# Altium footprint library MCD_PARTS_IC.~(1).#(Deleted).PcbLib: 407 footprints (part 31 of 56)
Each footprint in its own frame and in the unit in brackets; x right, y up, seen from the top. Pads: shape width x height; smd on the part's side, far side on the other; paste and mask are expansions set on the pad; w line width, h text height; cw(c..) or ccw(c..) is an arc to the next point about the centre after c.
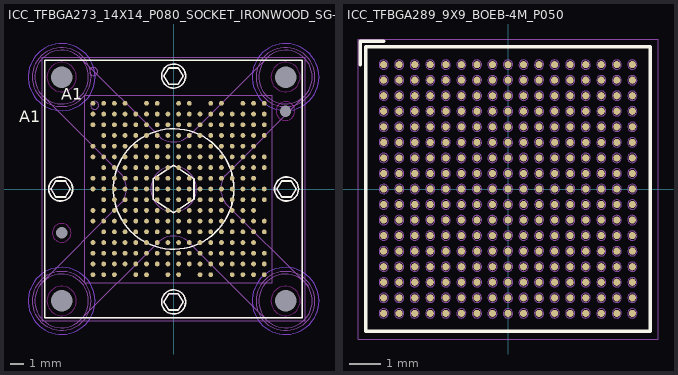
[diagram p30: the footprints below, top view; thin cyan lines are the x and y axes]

## ICC_TFBGA273_14X14_P080_SOCKET_IRONWOOD_SG-BGA-6112MF_WITHOUT-3D-SOCKET [mm] "MCD-03616"
height 1.2
pads (279):
  round 0.36 smd mask+0.05: A1(-6.025,6.4) A2(-5.225,6.4) A3(-4.425,6.4) A4(-3.625,6.4) A6(-2.025,6.4) A7(-1.225,6.4) A9(0.375,6.4) A10(1.175,6.4) A12(2.775,6.4) A13(3.575,6.4) A15(5.175,6.4) A16(5.975,6.4) A17(6.775,6.4) B1(-6.025,5.6) B2(-5.225,5.6) B3(-4.425,5.6) B4(-3.625,5.6) B5(-2.825,5.6) B6(-2.025,5.6) B7(-1.225,5.6) B8(-0.425,5.6) B9(0.375,5.6) B10(1.175,5.6) B11(1.975,5.6) B12(2.775,5.6) B13(3.575,5.6) B14(4.375,5.6) B15(5.175,5.6) B16(5.975,5.6) B17(6.775,5.6) C1(-6.025,4.8) C2(-5.225,4.8) C3(-4.425,4.8) C4(-3.625,4.8) C5(-2.825,4.8) C6(-2.025,4.8) C7(-1.225,4.8) C8(-0.425,4.8) C9(0.375,4.8) C10(1.175,4.8) C11(1.975,4.8) C12(2.775,4.8) C13(3.575,4.8) C14(4.375,4.8) C15(5.175,4.8) C16(5.975,4.8) C17(6.775,4.8) D2(-5.225,4) D3(-4.425,4) D4(-3.625,4) D5(-2.825,4) D6(-2.025,4) D7(-1.225,4) D8(-0.425,4) D9(0.375,4) D10(1.175,4) D11(1.975,4) D12(2.775,4) D13(3.575,4) D14(4.375,4) D15(5.175,4) D16(5.975,4) D17(6.775,4) E1(-6.025,3.2) E2(-5.225,3.2) E3(-4.425,3.2) E4(-3.625,3.2) E5(-2.825,3.2) E6(-2.025,3.2) E7(-1.225,3.2) E8(-0.425,3.2) E9(0.375,3.2) E10(1.175,3.2) E11(1.975,3.2) E12(2.775,3.2) E13(3.575,3.2) E14(4.375,3.2) E15(5.175,3.2) E16(5.975,3.2) F1(-6.025,2.4) F2(-5.225,2.4) F3(-4.425,2.4) F4(-3.625,2.4) F5(-2.825,2.4) F6(-2.025,2.4) F7(-1.225,2.4) F8(-0.425,2.4) F9(0.375,2.4) F10(1.175,2.4) F11(1.975,2.4) F12(2.775,2.4) F13(3.575,2.4) F14(4.375,2.4) F15(5.175,2.4) F16(5.975,2.4) F17(6.775,2.4) G2(-5.225,1.6) G3(-4.425,1.6) G4(-3.625,1.6) G5(-2.825,1.6) G6(-2.025,1.6) G7(-1.225,1.6) G8(-0.425,1.6) G9(0.375,1.6) G10(1.175,1.6) G11(1.975,1.6) G12(2.775,1.6) G13(3.575,1.6) G14(4.375,1.6) G15(5.175,1.6) G16(5.975,1.6) G17(6.775,1.6) H1(-6.025,0.8) H2(-5.225,0.8) H3(-4.425,0.8) H4(-3.625,0.8) H5(-2.825,0.8) H6(-2.025,0.8) H7(-1.225,0.8) H8(-0.425,0.8) H9(0.375,0.8) H10(1.175,0.8) H11(1.975,0.8) H12(2.775,0.8) H13(3.575,0.8) H14(4.375,0.8) H15(5.175,0.8) H16(5.975,0.8) J1(-6.025,0) J2(-5.225,0) J3(-4.425,0) J4(-3.625,0) J5(-2.825,0) J6(-2.025,0) J7(-1.225,0) J8(-0.425,0) J9(0.375,0) J10(1.175,0) J11(1.975,0) J12(2.775,0) J13(3.575,0) J14(4.375,0) J15(5.175,0) J16(5.975,0) J17(6.775,0) K2(-5.225,-0.8) K3(-4.425,-0.8) K4(-3.625,-0.8) K5(-2.825,-0.8) K6(-2.025,-0.8) K7(-1.225,-0.8) K8(-0.425,-0.8) K9(0.375,-0.8) K10(1.175,-0.8) K11(1.975,-0.8) K12(2.775,-0.8) K13(3.575,-0.8) K14(4.375,-0.8) K15(5.175,-0.8) K16(5.975,-0.8) K17(6.775,-0.8) L1(-6.025,-1.6) L2(-5.225,-1.6) L3(-4.425,-1.6) L4(-3.625,-1.6) L5(-2.825,-1.6) L6(-2.025,-1.6) L7(-1.225,-1.6) L8(-0.425,-1.6) L9(0.375,-1.6) L10(1.175,-1.6) L11(1.975,-1.6) L12(2.775,-1.6) L13(3.575,-1.6) L14(4.375,-1.6) L15(5.175,-1.6) L16(5.975,-1.6) M1(-6.025,-2.4) M2(-5.225,-2.4) M3(-4.425,-2.4) M4(-3.625,-2.4) M5(-2.825,-2.4) M6(-2.025,-2.4) M7(-1.225,-2.4) M8(-0.425,-2.4) M9(0.375,-2.4) M10(1.175,-2.4) M11(1.975,-2.4) M12(2.775,-2.4) M13(3.575,-2.4) M14(4.375,-2.4) M15(5.175,-2.4) M16(5.975,-2.4) M17(6.775,-2.4) N2(-5.225,-3.2) N3(-4.425,-3.2) N4(-3.625,-3.2) N5(-2.825,-3.2) N6(-2.025,-3.2) N7(-1.225,-3.2) N8(-0.425,-3.2) N9(0.375,-3.2) N10(1.175,-3.2) N11(1.975,-3.2) N12(2.775,-3.2) N13(3.575,-3.2) N14(4.375,-3.2) N15(5.175,-3.2) N16(5.975,-3.2) N17(6.775,-3.2) P1(-6.025,-4) P2(-5.225,-4) P3(-4.425,-4) P4(-3.625,-4) P5(-2.825,-4) P6(-2.025,-4) P7(-1.225,-4) P8(-0.425,-4) P9(0.375,-4) P10(1.175,-4) P11(1.975,-4) P12(2.775,-4) P13(3.575,-4) P14(4.375,-4) P15(5.175,-4) P16(5.975,-4) R1(-6.025,-4.8) R2(-5.225,-4.8) R3(-4.425,-4.8) R4(-3.625,-4.8) R5(-2.825,-4.8) R6(-2.025,-4.8) R7(-1.225,-4.8) R8(-0.425,-4.8) R9(0.375,-4.8) R10(1.175,-4.8) R11(1.975,-4.8) R12(2.775,-4.8) R13(3.575,-4.8) R14(4.375,-4.8) R15(5.175,-4.8) R16(5.975,-4.8) R17(6.775,-4.8) T1(-6.025,-5.6) T2(-5.225,-5.6) T3(-4.425,-5.6) T4(-3.625,-5.6) T5(-2.825,-5.6) T6(-2.025,-5.6) T7(-1.225,-5.6) T8(-0.425,-5.6) T9(0.375,-5.6) T10(1.175,-5.6) T11(1.975,-5.6) T12(2.775,-5.6) T13(3.575,-5.6) T14(4.375,-5.6) T15(5.175,-5.6) T16(5.975,-5.6) T17(6.775,-5.6) U1(-6.025,-6.4) U2(-5.225,-6.4) U3(-4.425,-6.4) U5(-2.825,-6.4) U6(-2.025,-6.4) U8(-0.425,-6.4) U9(0.375,-6.4) U11(1.975,-6.4) U12(2.775,-6.4) U14(4.375,-6.4) U15(5.175,-6.4) U16(5.975,-6.4) U17(6.775,-6.4)
  round 0 hole 1.61 unplated mask+0.05: NPTH1(-8.363,8.363) NPTH2(8.363,8.363) NPTH3(8.363,-8.363) NPTH4(-8.363,-8.363)
  round 0 hole 0.85 unplated mask+0.05: NPTH5(-8.363,-3.283) NPTH6(8.363,5.823)
Bottom Layer keep-out:
  circle w0.01: c-8.362,8.362 r2.5
  circle w0.01: c8.363,8.363 r2.5
  circle w0.01: c8.363,-8.363 r2.5
  circle w0.01: c-8.363,-8.363 r2.5
Top Overlay:
  circle w0.12: c0,0 r4.5
  circle w0.12: c-8.438,0 r0.9
  circle w0.12: c0,-8.438 r0.9
  circle w0.12: c8.438,0 r0.9
  circle w0.12: c0,8.437 r0.9
  lines w0.12: -9.613,-9.613 9.613,-9.613 9.613,9.613 -9.613,9.613 -9.613,-9.613 ; -9.158,0 -8.798,0.6 -8.078,0.6 -7.718,0 -8.078,-0.6 -8.798,-0.6 -9.158,0 ; -1.524,-0.762 0,-1.778 1.524,-0.762 1.524,0.762 0,1.778 -1.524,0.762 -1.524,-0.762 ; -0.72,-8.438 -0.36,-7.838 0.36,-7.838 0.72,-8.438 0.36,-9.038 -0.36,-9.038 -0.72,-8.438 ; -0.72,8.437 -0.36,7.837 0.36,7.837 0.72,8.437 0.36,9.037 -0.36,9.037 -0.72,8.437 ; 7.718,0 8.078,0.6 8.798,0.6 9.158,0 8.798,-0.6 8.078,-0.6 7.718,0
  text "A1" at -8.4,6.375 h1.5
  text "A1" at -11.55,4.675 h1.5
Bottom Overlay:
  circle w0.12: c-8.363,8.363 r2.5
  circle w0.12: c-8.362,-8.362 r2.5
  circle w0.12: c8.362,-8.362 r2.5
  circle w0.12: c8.363,8.363 r2.5
Keep-Out Layer:
  circle w0.01: c8.363,5.823 r0.7
  circle w0.01: c-8.363,-3.283 r0.7
  circle w0.01: c-8.362,8.362 r1.1
  circle w0.01: c8.363,8.363 r1.1
  circle w0.01: c8.362,-8.362 r1.1
  circle w0.01: c-8.363,-8.363 r1.1
M14-Top Assembly:
  circle w0.01: c-5.9,6.25 r0.3
  circle w0.01: c0,0 r4.5
  circle w0.01: c-8.438,0 r0.9
  circle w0.01: c0,-8.438 r0.9
  circle w0.01: c8.438,0 r0.9
  circle w0.01: c0,8.437 r0.9
  circle w0.01: c-5.975,8.775 r0.3
  lines w0.01: -9.613,-9.613 9.613,-9.613 9.613,3.562 9.613,9.613 -9.613,9.613 -9.613,-9.613 ; -9.158,0 -8.798,-0.6 -8.078,-0.6 -7.718,0 -8.078,0.6 -8.798,0.6 -9.158,0 ; -6.625,-7 7.375,-7 7.375,7 -6.625,7 -6.625,-7 ; -1.524,-0.762 0,-1.778 1.524,-0.762 1.524,0.762 0,1.778 -1.524,0.762 -1.524,-0.762 ; -0.72,-8.438 -0.36,-9.038 0.36,-9.038 0.72,-8.438 0.36,-7.838 -0.36,-7.838 -0.72,-8.438 ; -0.72,8.437 -0.36,9.037 0.36,9.037 0.72,8.437 0.36,7.837 -0.36,7.837 -0.72,8.437 ; 7.718,0 8.078,-0.6 8.798,-0.6 9.158,0 8.798,0.6 8.078,0.6 7.718,0
  text "'.Designator'" at 0,0 h0.75
M15-Bottom Assembly:
  circle w0.01: c-8.362,8.362 r2
  circle w0.01: c-8.362,-8.362 r2
  circle w0.01: c8.363,-8.363 r2
  circle w0.01: c8.362,8.362 r2
  lines w0.01: -10.044,7.235 -3.82,1.011 ; -9.929,-7.075 -3.82,-0.967 ; -7.235,-10.044 -1.011,-3.82 ; -7.075,9.929 -0.967,3.82 ; -3.848,1.029 cw(c-5.325,0) -3.826,-0.996 ; -1.029,-3.848 cw(c0,-5.325) 0.996,-3.826 ; -0.996,3.826 ccw(c0,5.325) 1.029,3.848 ; 0.967,-3.82 7.075,-9.929 ; 1.011,3.82 7.235,10.044 ; 3.82,-1.011 10.044,-7.235 ; 3.82,0.967 9.928,7.075 ; 3.826,0.996 ccw(c5.325,0) 3.848,-1.029
M16-Top Courtyard:
  lines w0.01: -9.825,-9.825 -9.825,9.825 9.825,9.825 9.825,-9.825 -9.825,-9.825
M17-Bottom Courtyard:
  circle w0.01: c0,0 r1.7
  circle w0.01: c-8.362,8.362 r2.2
  circle w0.01: c8.362,8.362 r2.2
  circle w0.01: c8.362,-8.362 r2.2
  circle w0.01: c-8.362,-8.362 r2.2
3D body: height 0.37, standoff -0.03, extent -0.625,-6.6 -0.225,-6.2
3D body: height 0.37, standoff -0.03, extent 6.575,-6.6 6.975,-6.2
3D body: height 0.37, standoff -0.03, extent 5.775,-6.6 6.175,-6.2
3D body: height 0.37, standoff -0.03, extent 4.975,-6.6 5.375,-6.2
3D body: height 0.37, standoff -0.03, extent 4.175,-6.6 4.575,-6.2
3D body: height 0.37, standoff -0.03, extent 2.575,-6.6 2.975,-6.2
3D body: height 0.37, standoff -0.03, extent 1.775,-6.6 2.175,-6.2
3D body: height 0.37, standoff -0.03, extent 0.175,-6.6 0.575,-6.2
3D body: height 0.37, standoff -0.03, extent -2.225,-6.6 -1.825,-6.2
3D body: height 0.37, standoff -0.03, extent -3.025,-6.6 -2.625,-6.2
3D body: height 0.37, standoff -0.03, extent -4.625,-6.6 -4.225,-6.2
3D body: height 0.37, standoff -0.03, extent -5.425,-6.6 -5.025,-6.2
3D body: height 0.37, standoff -0.03, extent -6.225,-6.6 -5.825,-6.2
3D body: height 0.37, standoff -0.03, extent 6.575,-5.8 6.975,-5.4
3D body: height 0.37, standoff -0.03, extent 5.775,-5.8 6.175,-5.4
3D body: height 0.37, standoff -0.03, extent 4.975,-5.8 5.375,-5.4
3D body: height 0.37, standoff -0.03, extent 4.175,-5.8 4.575,-5.4
3D body: height 0.37, standoff -0.03, extent 3.375,-5.8 3.775,-5.4
3D body: height 0.37, standoff -0.03, extent 2.575,-5.8 2.975,-5.4
3D body: height 0.37, standoff -0.03, extent 1.775,-5.8 2.175,-5.4
3D body: height 0.37, standoff -0.03, extent 0.975,-5.8 1.375,-5.4
3D body: height 0.37, standoff -0.03, extent 0.175,-5.8 0.575,-5.4
3D body: height 0.37, standoff -0.03, extent -0.625,-5.8 -0.225,-5.4
3D body: height 0.37, standoff -0.03, extent -1.425,-5.8 -1.025,-5.4
3D body: height 0.37, standoff -0.03, extent -2.225,-5.8 -1.825,-5.4
3D body: height 0.37, standoff -0.03, extent -3.025,-5.8 -2.625,-5.4
3D body: height 0.37, standoff -0.03, extent -3.825,-5.8 -3.425,-5.4
3D body: height 0.37, standoff -0.03, extent -4.625,-5.8 -4.225,-5.4
3D body: height 0.37, standoff -0.03, extent -5.425,-5.8 -5.025,-5.4
3D body: height 0.37, standoff -0.03, extent -6.225,-5.8 -5.825,-5.4
3D body: height 0.37, standoff -0.03, extent 6.575,-5 6.975,-4.6
3D body: height 0.37, standoff -0.03, extent 5.775,-5 6.175,-4.6
3D body: height 0.37, standoff -0.03, extent 4.975,-5 5.375,-4.6
3D body: height 0.37, standoff -0.03, extent 4.175,-5 4.575,-4.6
3D body: height 0.37, standoff -0.03, extent 3.375,-5 3.775,-4.6
3D body: height 0.37, standoff -0.03, extent 2.575,-5 2.975,-4.6
3D body: height 0.37, standoff -0.03, extent 1.775,-5 2.175,-4.6
3D body: height 0.37, standoff -0.03, extent 0.975,-5 1.375,-4.6
3D body: height 0.37, standoff -0.03, extent 0.175,-5 0.575,-4.6
3D body: height 0.37, standoff -0.03, extent -0.625,-5 -0.225,-4.6
3D body: height 0.37, standoff -0.03, extent -1.425,-5 -1.025,-4.6
3D body: height 0.37, standoff -0.03, extent -2.225,-5 -1.825,-4.6
3D body: height 0.37, standoff -0.03, extent -3.025,-5 -2.625,-4.6
3D body: height 0.37, standoff -0.03, extent -3.825,-5 -3.425,-4.6
3D body: height 0.37, standoff -0.03, extent -4.625,-5 -4.225,-4.6
3D body: height 0.37, standoff -0.03, extent -5.425,-5 -5.025,-4.6
3D body: height 0.37, standoff -0.03, extent -6.225,-5 -5.825,-4.6
3D body: height 0.37, standoff -0.03, extent 5.775,-4.2 6.175,-3.8
3D body: height 0.37, standoff -0.03, extent 4.975,-4.2 5.375,-3.8
3D body: height 0.37, standoff -0.03, extent 4.175,-4.2 4.575,-3.8
3D body: height 0.37, standoff -0.03, extent 3.375,-4.2 3.775,-3.8
3D body: height 0.37, standoff -0.03, extent 2.575,-4.2 2.975,-3.8
3D body: height 0.37, standoff -0.03, extent 1.775,-4.2 2.175,-3.8
3D body: height 0.37, standoff -0.03, extent 0.975,-4.2 1.375,-3.8
3D body: height 0.37, standoff -0.03, extent 0.175,-4.2 0.575,-3.8
3D body: height 0.37, standoff -0.03, extent -0.625,-4.2 -0.225,-3.8
3D body: height 0.37, standoff -0.03, extent -1.425,-4.2 -1.025,-3.8
3D body: height 0.37, standoff -0.03, extent -2.225,-4.2 -1.825,-3.8
3D body: height 0.37, standoff -0.03, extent -3.025,-4.2 -2.625,-3.8
3D body: height 0.37, standoff -0.03, extent -3.825,-4.2 -3.425,-3.8
3D body: height 0.37, standoff -0.03, extent -4.625,-4.2 -4.225,-3.8
3D body: height 0.37, standoff -0.03, extent -5.425,-4.2 -5.025,-3.8
3D body: height 0.37, standoff -0.03, extent -6.225,-4.2 -5.825,-3.8
3D body: height 0.37, standoff -0.03, extent 6.575,-3.4 6.975,-3
3D body: height 0.37, standoff -0.03, extent 5.775,-3.4 6.175,-3
3D body: height 0.37, standoff -0.03, extent 4.975,-3.4 5.375,-3
3D body: height 0.37, standoff -0.03, extent 4.175,-3.4 4.575,-3
3D body: height 0.37, standoff -0.03, extent 3.375,-3.4 3.775,-3
3D body: height 0.37, standoff -0.03, extent 2.575,-3.4 2.975,-3
3D body: height 0.37, standoff -0.03, extent 1.775,-3.4 2.175,-3
3D body: height 0.37, standoff -0.03, extent 0.975,-3.4 1.375,-3
3D body: height 0.37, standoff -0.03, extent 0.175,-3.4 0.575,-3
3D body: height 0.37, standoff -0.03, extent -0.625,-3.4 -0.225,-3
3D body: height 0.37, standoff -0.03, extent -1.425,-3.4 -1.025,-3
3D body: height 0.37, standoff -0.03, extent -2.225,-3.4 -1.825,-3
3D body: height 0.37, standoff -0.03, extent -3.025,-3.4 -2.625,-3
3D body: height 0.37, standoff -0.03, extent -3.825,-3.4 -3.425,-3
3D body: height 0.37, standoff -0.03, extent -4.625,-3.4 -4.225,-3
3D body: height 0.37, standoff -0.03, extent -5.425,-3.4 -5.025,-3
3D body: height 0.37, standoff -0.03, extent 6.575,-2.6 6.975,-2.2
3D body: height 0.37, standoff -0.03, extent 5.775,-2.6 6.175,-2.2
3D body: height 0.37, standoff -0.03, extent 4.975,-2.6 5.375,-2.2
3D body: height 0.37, standoff -0.03, extent 4.175,-2.6 4.575,-2.2
3D body: height 0.37, standoff -0.03, extent 3.375,-2.6 3.775,-2.2
3D body: height 0.37, standoff -0.03, extent 2.575,-2.6 2.975,-2.2
3D body: height 0.37, standoff -0.03, extent 1.775,-2.6 2.175,-2.2
3D body: height 0.37, standoff -0.03, extent 0.975,-2.6 1.375,-2.2
3D body: height 0.37, standoff -0.03, extent 0.175,-2.6 0.575,-2.2
3D body: height 0.37, standoff -0.03, extent -0.625,-2.6 -0.225,-2.2
3D body: height 0.37, standoff -0.03, extent -1.425,-2.6 -1.025,-2.2
3D body: height 0.37, standoff -0.03, extent -2.225,-2.6 -1.825,-2.2
3D body: height 0.37, standoff -0.03, extent -3.025,-2.6 -2.625,-2.2
3D body: height 0.37, standoff -0.03, extent -3.825,-2.6 -3.425,-2.2
3D body: height 0.37, standoff -0.03, extent -4.625,-2.6 -4.225,-2.2
3D body: height 0.37, standoff -0.03, extent -5.425,-2.6 -5.025,-2.2
3D body: height 0.37, standoff -0.03, extent -6.225,-2.6 -5.825,-2.2
3D body: height 0.37, standoff -0.03, extent 5.775,-1.8 6.175,-1.4
3D body: height 0.37, standoff -0.03, extent 4.975,-1.8 5.375,-1.4
3D body: height 0.37, standoff -0.03, extent 4.175,-1.8 4.575,-1.4
3D body: height 0.37, standoff -0.03, extent 3.375,-1.8 3.775,-1.4
3D body: height 0.37, standoff -0.03, extent 2.575,-1.8 2.975,-1.4
3D body: height 0.37, standoff -0.03, extent 1.775,-1.8 2.175,-1.4
3D body: height 0.37, standoff -0.03, extent 0.975,-1.8 1.375,-1.4
3D body: height 0.37, standoff -0.03, extent 0.175,-1.8 0.575,-1.4
3D body: height 0.37, standoff -0.03, extent -0.625,-1.8 -0.225,-1.4
3D body: height 0.37, standoff -0.03, extent -1.425,-1.8 -1.025,-1.4
3D body: height 0.37, standoff -0.03, extent -2.225,-1.8 -1.825,-1.4
3D body: height 0.37, standoff -0.03, extent -3.025,-1.8 -2.625,-1.4
3D body: height 0.37, standoff -0.03, extent -3.825,-1.8 -3.425,-1.4
3D body: height 0.37, standoff -0.03, extent -4.625,-1.8 -4.225,-1.4
3D body: height 0.37, standoff -0.03, extent -5.425,-1.8 -5.025,-1.4
3D body: height 0.37, standoff -0.03, extent -6.225,-1.8 -5.825,-1.4
3D body: height 0.37, standoff -0.03, extent 6.575,-1 6.975,-0.6
3D body: height 0.37, standoff -0.03, extent 5.775,-1 6.175,-0.6
3D body: height 0.37, standoff -0.03, extent 4.975,-1 5.375,-0.6
3D body: height 0.37, standoff -0.03, extent 4.175,-1 4.575,-0.6
3D body: height 0.37, standoff -0.03, extent 3.375,-1 3.775,-0.6
3D body: height 0.37, standoff -0.03, extent 2.575,-1 2.975,-0.6
3D body: height 0.37, standoff -0.03, extent 1.775,-1 2.175,-0.6
3D body: height 0.37, standoff -0.03, extent 0.975,-1 1.375,-0.6
3D body: height 0.37, standoff -0.03, extent 0.175,-1 0.575,-0.6
3D body: height 0.37, standoff -0.03, extent -0.625,-1 -0.225,-0.6
3D body: height 0.37, standoff -0.03, extent -1.425,-1 -1.025,-0.6
3D body: height 0.37, standoff -0.03, extent -2.225,-1 -1.825,-0.6
3D body: height 0.37, standoff -0.03, extent -3.025,-1 -2.625,-0.6
3D body: height 0.37, standoff -0.03, extent -3.825,-1 -3.425,-0.6
3D body: height 0.37, standoff -0.03, extent -4.625,-1 -4.225,-0.6
3D body: height 0.37, standoff -0.03, extent -5.425,-1 -5.025,-0.6
3D body: height 0.37, standoff -0.03, extent 6.575,-0.2 6.975,0.2
3D body: height 0.37, standoff -0.03, extent 5.775,-0.2 6.175,0.2
3D body: height 0.37, standoff -0.03, extent 4.975,-0.2 5.375,0.2
3D body: height 0.37, standoff -0.03, extent 4.175,-0.2 4.575,0.2
3D body: height 0.37, standoff -0.03, extent 3.375,-0.2 3.775,0.2
3D body: height 0.37, standoff -0.03, extent 2.575,-0.2 2.975,0.2
3D body: height 0.37, standoff -0.03, extent 1.775,-0.2 2.175,0.2
3D body: height 0.37, standoff -0.03, extent 0.975,-0.2 1.375,0.2
3D body: height 0.37, standoff -0.03, extent 0.175,-0.2 0.575,0.2
3D body: height 0.37, standoff -0.03, extent -0.625,-0.2 -0.225,0.2
3D body: height 0.37, standoff -0.03, extent -1.425,-0.2 -1.025,0.2
3D body: height 0.37, standoff -0.03, extent -2.225,-0.2 -1.825,0.2
3D body: height 0.37, standoff -0.03, extent -3.025,-0.2 -2.625,0.2
3D body: height 0.37, standoff -0.03, extent -3.825,-0.2 -3.425,0.2
3D body: height 0.37, standoff -0.03, extent -4.625,-0.2 -4.225,0.2
3D body: height 0.37, standoff -0.03, extent -5.425,-0.2 -5.025,0.2
3D body: height 0.37, standoff -0.03, extent -6.225,-0.2 -5.825,0.2
3D body: height 0.37, standoff -0.03, extent 5.775,0.6 6.175,1
3D body: height 0.37, standoff -0.03, extent 4.975,0.6 5.375,1
3D body: height 0.37, standoff -0.03, extent 4.175,0.6 4.575,1
3D body: height 0.37, standoff -0.03, extent 3.375,0.6 3.775,1
3D body: height 0.37, standoff -0.03, extent 2.575,0.6 2.975,1
3D body: height 0.37, standoff -0.03, extent 1.775,0.6 2.175,1
3D body: height 0.37, standoff -0.03, extent 0.975,0.6 1.375,1
3D body: height 0.37, standoff -0.03, extent 0.175,0.6 0.575,1
3D body: height 0.37, standoff -0.03, extent -0.625,0.6 -0.225,1
3D body: height 0.37, standoff -0.03, extent -1.425,0.6 -1.025,1
3D body: height 0.37, standoff -0.03, extent -2.225,0.6 -1.825,1
3D body: height 0.37, standoff -0.03, extent -3.025,0.6 -2.625,1
3D body: height 0.37, standoff -0.03, extent -3.825,0.6 -3.425,1
3D body: height 0.37, standoff -0.03, extent -4.625,0.6 -4.225,1
3D body: height 0.37, standoff -0.03, extent -5.425,0.6 -5.025,1
3D body: height 0.37, standoff -0.03, extent -6.225,0.6 -5.825,1
3D body: height 0.37, standoff -0.03, extent 6.575,1.4 6.975,1.8
3D body: height 0.37, standoff -0.03, extent 5.775,1.4 6.175,1.8
3D body: height 0.37, standoff -0.03, extent 4.975,1.4 5.375,1.8
3D body: height 0.37, standoff -0.03, extent 4.175,1.4 4.575,1.8
3D body: height 0.37, standoff -0.03, extent 3.375,1.4 3.775,1.8
3D body: height 0.37, standoff -0.03, extent 2.575,1.4 2.975,1.8
3D body: height 0.37, standoff -0.03, extent 1.775,1.4 2.175,1.8
3D body: height 0.37, standoff -0.03, extent 0.975,1.4 1.375,1.8
3D body: height 0.37, standoff -0.03, extent 0.175,1.4 0.575,1.8
3D body: height 0.37, standoff -0.03, extent -0.625,1.4 -0.225,1.8
3D body: height 0.37, standoff -0.03, extent -1.425,1.4 -1.025,1.8
3D body: height 0.37, standoff -0.03, extent -2.225,1.4 -1.825,1.8
3D body: height 0.37, standoff -0.03, extent -3.025,1.4 -2.625,1.8
3D body: height 0.37, standoff -0.03, extent -3.825,1.4 -3.425,1.8
3D body: height 0.37, standoff -0.03, extent -4.625,1.4 -4.225,1.8
3D body: height 0.37, standoff -0.03, extent -5.425,1.4 -5.025,1.8
3D body: height 0.37, standoff -0.03, extent 6.575,2.2 6.975,2.6
3D body: height 0.37, standoff -0.03, extent 5.775,2.2 6.175,2.6
3D body: height 0.37, standoff -0.03, extent 4.975,2.2 5.375,2.6
3D body: height 0.37, standoff -0.03, extent 4.175,2.2 4.575,2.6
3D body: height 0.37, standoff -0.03, extent 3.375,2.2 3.775,2.6
3D body: height 0.37, standoff -0.03, extent 2.575,2.2 2.975,2.6
3D body: height 0.37, standoff -0.03, extent 1.775,2.2 2.175,2.6
3D body: height 0.37, standoff -0.03, extent 0.975,2.2 1.375,2.6
3D body: height 0.37, standoff -0.03, extent 0.175,2.2 0.575,2.6
3D body: height 0.37, standoff -0.03, extent -0.625,2.2 -0.225,2.6
3D body: height 0.37, standoff -0.03, extent -1.425,2.2 -1.025,2.6
3D body: height 0.37, standoff -0.03, extent -2.225,2.2 -1.825,2.6
3D body: height 0.37, standoff -0.03, extent -3.025,2.2 -2.625,2.6
3D body: height 0.37, standoff -0.03, extent -3.825,2.2 -3.425,2.6
3D body: height 0.37, standoff -0.03, extent -4.625,2.2 -4.225,2.6
3D body: height 0.37, standoff -0.03, extent -5.425,2.2 -5.025,2.6
3D body: height 0.37, standoff -0.03, extent -6.225,2.2 -5.825,2.6
3D body: height 0.37, standoff -0.03, extent 5.775,3 6.175,3.4
3D body: height 0.37, standoff -0.03, extent 4.975,3 5.375,3.4
3D body: height 0.37, standoff -0.03, extent 4.175,3 4.575,3.4
3D body: height 0.37, standoff -0.03, extent 3.375,3 3.775,3.4
3D body: height 0.37, standoff -0.03, extent 2.575,3 2.975,3.4
3D body: height 0.37, standoff -0.03, extent 1.775,3 2.175,3.4
3D body: height 0.37, standoff -0.03, extent 0.975,3 1.375,3.4
3D body: height 0.37, standoff -0.03, extent 0.175,3 0.575,3.4
3D body: height 0.37, standoff -0.03, extent -0.625,3 -0.225,3.4
3D body: height 0.37, standoff -0.03, extent -1.425,3 -1.025,3.4
3D body: height 0.37, standoff -0.03, extent -2.225,3 -1.825,3.4
3D body: height 0.37, standoff -0.03, extent -3.025,3 -2.625,3.4
3D body: height 0.37, standoff -0.03, extent -3.825,3 -3.425,3.4
3D body: height 0.37, standoff -0.03, extent -4.625,3 -4.225,3.4
3D body: height 0.37, standoff -0.03, extent -5.425,3 -5.025,3.4
3D body: height 0.37, standoff -0.03, extent -6.225,3 -5.825,3.4
3D body: height 0.37, standoff -0.03, extent 6.575,3.8 6.975,4.2
3D body: height 0.37, standoff -0.03, extent 5.775,3.8 6.175,4.2
3D body: height 0.37, standoff -0.03, extent 4.975,3.8 5.375,4.2
3D body: height 0.37, standoff -0.03, extent 4.175,3.8 4.575,4.2
3D body: height 0.37, standoff -0.03, extent 3.375,3.8 3.775,4.2
3D body: height 0.37, standoff -0.03, extent 2.575,3.8 2.975,4.2
3D body: height 0.37, standoff -0.03, extent 1.775,3.8 2.175,4.2
3D body: height 0.37, standoff -0.03, extent 0.975,3.8 1.375,4.2
3D body: height 0.37, standoff -0.03, extent 0.175,3.8 0.575,4.2
3D body: height 0.37, standoff -0.03, extent -0.625,3.8 -0.225,4.2
3D body: height 0.37, standoff -0.03, extent -1.425,3.8 -1.025,4.2
3D body: height 0.37, standoff -0.03, extent -2.225,3.8 -1.825,4.2
3D body: height 0.37, standoff -0.03, extent -3.025,3.8 -2.625,4.2
3D body: height 0.37, standoff -0.03, extent -3.825,3.8 -3.425,4.2
3D body: height 0.37, standoff -0.03, extent -4.625,3.8 -4.225,4.2
3D body: height 0.37, standoff -0.03, extent -5.425,3.8 -5.025,4.2
3D body: height 0.37, standoff -0.03, extent 6.575,4.6 6.975,5
3D body: height 0.37, standoff -0.03, extent 5.775,4.6 6.175,5
3D body: height 0.37, standoff -0.03, extent 4.975,4.6 5.375,5
3D body: height 0.37, standoff -0.03, extent 4.175,4.6 4.575,5
3D body: height 0.37, standoff -0.03, extent 3.375,4.6 3.775,5
3D body: height 0.37, standoff -0.03, extent 2.575,4.6 2.975,5
3D body: height 0.37, standoff -0.03, extent 1.775,4.6 2.175,5
3D body: height 0.37, standoff -0.03, extent 0.975,4.6 1.375,5
3D body: height 0.37, standoff -0.03, extent 0.175,4.6 0.575,5
3D body: height 0.37, standoff -0.03, extent -0.625,4.6 -0.225,5
3D body: height 0.37, standoff -0.03, extent -1.425,4.6 -1.025,5
3D body: height 0.37, standoff -0.03, extent -2.225,4.6 -1.825,5
3D body: height 0.37, standoff -0.03, extent -3.025,4.6 -2.625,5
3D body: height 0.37, standoff -0.03, extent -3.825,4.6 -3.425,5
3D body: height 0.37, standoff -0.03, extent -4.625,4.6 -4.225,5
3D body: height 0.37, standoff -0.03, extent -5.425,4.6 -5.025,5
3D body: height 0.37, standoff -0.03, extent -6.225,4.6 -5.825,5
3D body: height 0.37, standoff -0.03, extent 6.575,5.4 6.975,5.8
3D body: height 0.37, standoff -0.03, extent 5.775,5.4 6.175,5.8
3D body: height 0.37, standoff -0.03, extent 4.975,5.4 5.375,5.8
3D body: height 0.37, standoff -0.03, extent 4.175,5.4 4.575,5.8
3D body: height 0.37, standoff -0.03, extent 3.375,5.4 3.775,5.8
3D body: height 0.37, standoff -0.03, extent 2.575,5.4 2.975,5.8
3D body: height 0.37, standoff -0.03, extent 1.775,5.4 2.175,5.8
3D body: height 0.37, standoff -0.03, extent 0.975,5.4 1.375,5.8
3D body: height 0.37, standoff -0.03, extent 0.175,5.4 0.575,5.8
3D body: height 0.37, standoff -0.03, extent -0.625,5.4 -0.225,5.8
3D body: height 0.37, standoff -0.03, extent -1.425,5.4 -1.025,5.8
3D body: height 0.37, standoff -0.03, extent -2.225,5.4 -1.825,5.8
3D body: height 0.37, standoff -0.03, extent -3.025,5.4 -2.625,5.8
3D body: height 0.37, standoff -0.03, extent -3.825,5.4 -3.425,5.8
3D body: height 0.37, standoff -0.03, extent -4.625,5.4 -4.225,5.8
3D body: height 0.37, standoff -0.03, extent -5.425,5.4 -5.025,5.8
3D body: height 0.37, standoff -0.03, extent -6.225,5.4 -5.825,5.8
3D body: height 0.37, standoff -0.03, extent 6.575,6.2 6.975,6.6
3D body: height 0.37, standoff -0.03, extent 5.775,6.2 6.175,6.6
3D body: height 0.37, standoff -0.03, extent 4.975,6.2 5.375,6.6
3D body: height 0.37, standoff -0.03, extent 3.375,6.2 3.775,6.6
3D body: height 0.37, standoff -0.03, extent 2.575,6.2 2.975,6.6
3D body: height 0.37, standoff -0.03, extent 0.975,6.2 1.375,6.6
3D body: height 0.37, standoff -0.03, extent 0.175,6.2 0.575,6.6
3D body: height 0.37, standoff -0.03, extent -1.425,6.2 -1.025,6.6
3D body: height 0.37, standoff -0.03, extent -2.225,6.2 -1.825,6.6
3D body: height 0.37, standoff -0.03, extent -3.825,6.2 -3.425,6.6
3D body: height 0.37, standoff -0.03, extent -4.625,6.2 -4.225,6.6
3D body: height 0.37, standoff -0.03, extent -5.425,6.2 -5.025,6.6
3D body: height 0.37, standoff -0.03, extent -6.225,6.2 -5.825,6.6
3D body: height 1.21, standoff 1.2, extent -6.3,5.85 -5.5,6.65
3D body: height 1.2, standoff 0.29, extent -6.625,-7 7.375,7

## ICC_TFBGA289_9X9_BOEB-4M_P050 [mm] "MCD-02673"
height 1.2
pads (289):
  round 0.23 smd paste+0.025 mask+0.05: A1(-4,4) A2(-3.5,4) A3(-3,4) A4(-2.5,4) A5(-2,4) A6(-1.5,4) A7(-1,4) A8(-0.5,4) A9(0,4) A10(0.5,4) A11(1,4) A12(1.5,4) A13(2,4) A14(2.5,4) A15(3,4) A16(3.5,4) A17(4,4) B1(-4,3.5) B2(-3.5,3.5) B3(-3,3.5) B4(-2.5,3.5) B5(-2,3.5) B6(-1.5,3.5) B7(-1,3.5) B8(-0.5,3.5) B9(0,3.5) B10(0.5,3.5) B11(1,3.5) B12(1.5,3.5) B13(2,3.5) B14(2.5,3.5) B15(3,3.5) B16(3.5,3.5) B17(4,3.5) C1(-4,3) C2(-3.5,3) C3(-3,3) C4(-2.5,3) C5(-2,3) C6(-1.5,3) C7(-1,3) C8(-0.5,3) C9(0,3) C10(0.5,3) C11(1,3) C12(1.5,3) C13(2,3) C14(2.5,3) C15(3,3) C16(3.5,3) C17(4,3) D1(-4,2.5) D2(-3.5,2.5) D3(-3,2.5) D4(-2.5,2.5) D5(-2,2.5) D6(-1.5,2.5) D7(-1,2.5) D8(-0.5,2.5) D9(0,2.5) D10(0.5,2.5) D11(1,2.5) D12(1.5,2.5) D13(2,2.5) D14(2.5,2.5) D15(3,2.5) D16(3.5,2.5) D17(4,2.5) E1(-4,2) E2(-3.5,2) E3(-3,2) E4(-2.5,2) E5(-2,2) E6(-1.5,2) E7(-1,2) E8(-0.5,2) E9(0,2) E10(0.5,2) E11(1,2) E12(1.5,2) E13(2,2) E14(2.5,2) E15(3,2) E16(3.5,2) E17(4,2) F1(-4,1.5) F2(-3.5,1.5) F3(-3,1.5) F4(-2.5,1.5) F5(-2,1.5) F6(-1.5,1.5) F7(-1,1.5) F8(-0.5,1.5) F9(0,1.5) F10(0.5,1.5) F11(1,1.5) F12(1.5,1.5) F13(2,1.5) F14(2.5,1.5) F15(3,1.5) F16(3.5,1.5) F17(4,1.5) G1(-4,1) G2(-3.5,1) G3(-3,1) G4(-2.5,1) G5(-2,1) G6(-1.5,1) G7(-1,1) G8(-0.5,1) G9(0,1) G10(0.5,1) G11(1,1) G12(1.5,1) G13(2,1) G14(2.5,1) G15(3,1) G16(3.5,1) G17(4,1) H1(-4,0.5) H2(-3.5,0.5) H3(-3,0.5) H4(-2.5,0.5) H5(-2,0.5) H6(-1.5,0.5) H7(-1,0.5) H8(-0.5,0.5) H9(0,0.5) H10(0.5,0.5) H11(1,0.5) H12(1.5,0.5) H13(2,0.5) H14(2.5,0.5) H15(3,0.5) H16(3.5,0.5) H17(4,0.5) J1(-4,0) J2(-3.5,0) J3(-3,0) J4(-2.5,0) J5(-2,0) J6(-1.5,0) J7(-1,0) J8(-0.5,0) J9(0,0) J10(0.5,0) J11(1,0) J12(1.5,0) J13(2,0) J14(2.5,0) J15(3,0) J16(3.5,0) J17(4,0) K1(-4,-0.5) K2(-3.5,-0.5) K3(-3,-0.5) K4(-2.5,-0.5) K5(-2,-0.5) K6(-1.5,-0.5) K7(-1,-0.5) K8(-0.5,-0.5) K9(0,-0.5) K10(0.5,-0.5) K11(1,-0.5) K12(1.5,-0.5) K13(2,-0.5) K14(2.5,-0.5) K15(3,-0.5) K16(3.5,-0.5) K17(4,-0.5) L1(-4,-1) L2(-3.5,-1) L3(-3,-1) L4(-2.5,-1) L5(-2,-1) L6(-1.5,-1) L7(-1,-1) L8(-0.5,-1) L9(0,-1) L10(0.5,-1) L11(1,-1) L12(1.5,-1) L13(2,-1) L14(2.5,-1) L15(3,-1) L16(3.5,-1) L17(4,-1) M1(-4,-1.5) M2(-3.5,-1.5) M3(-3,-1.5) M4(-2.5,-1.5) M5(-2,-1.5) M6(-1.5,-1.5) M7(-1,-1.5) M8(-0.5,-1.5) M9(0,-1.5) M10(0.5,-1.5) M11(1,-1.5) M12(1.5,-1.5) M13(2,-1.5) M14(2.5,-1.5) M15(3,-1.5) M16(3.5,-1.5) M17(4,-1.5) N1(-4,-2) N2(-3.5,-2) N3(-3,-2) N4(-2.5,-2) N5(-2,-2) N6(-1.5,-2) N7(-1,-2) N8(-0.5,-2) N9(0,-2) N10(0.5,-2) N11(1,-2) N12(1.5,-2) N13(2,-2) N14(2.5,-2) N15(3,-2) N16(3.5,-2) N17(4,-2) P1(-4,-2.5) P2(-3.5,-2.5) P3(-3,-2.5) P4(-2.5,-2.5) P5(-2,-2.5) P6(-1.5,-2.5) P7(-1,-2.5) P8(-0.5,-2.5) P9(0,-2.5) P10(0.5,-2.5) P11(1,-2.5) P12(1.5,-2.5) P13(2,-2.5) P14(2.5,-2.5) P15(3,-2.5) P16(3.5,-2.5) P17(4,-2.5) R1(-4,-3) R2(-3.5,-3) R3(-3,-3) R4(-2.5,-3) R5(-2,-3) R6(-1.5,-3) R7(-1,-3) R8(-0.5,-3) R9(0,-3) R10(0.5,-3) R11(1,-3) R12(1.5,-3) R13(2,-3) R14(2.5,-3) R15(3,-3) R16(3.5,-3) R17(4,-3) T1(-4,-3.5) T2(-3.5,-3.5) T3(-3,-3.5) T4(-2.5,-3.5) T5(-2,-3.5) T6(-1.5,-3.5) T7(-1,-3.5) T8(-0.5,-3.5) T9(0,-3.5) T10(0.5,-3.5) T11(1,-3.5) T12(1.5,-3.5) T13(2,-3.5) T14(2.5,-3.5) T15(3,-3.5) T16(3.5,-3.5) T17(4,-3.5) U1(-4,-4) U2(-3.5,-4) U3(-3,-4) U4(-2.5,-4) U5(-2,-4) U6(-1.5,-4) U7(-1,-4) U8(-0.5,-4) U9(0,-4) U10(0.5,-4) U11(1,-4) U12(1.5,-4) U13(2,-4) U14(2.5,-4) U15(3,-4) U16(3.5,-4) U17(4,-4)
Top Overlay:
  lines w0.12: -4.75,4 -4.75,4.75 -4,4.75 ; -4.575,-4.575 4.575,-4.575 4.575,4.575 -4.575,4.575 -4.575,-4.575
M14-Top Assembly:
  drawing of 293 lines, arcs and shapes, not listed
  text "A1" at -4.25,3.85 h0.5
  text "'.Designator'" at -2,-0.5 h0.75
M16-Top Courtyard:
  lines w0.01: -4.825,-4.825 4.825,-4.825 4.825,4.825 -4.825,4.825 -4.825,-4.825
3D body: height 0.27, standoff -0.03, extent 3.85,-4.15 4.15,-3.85
3D body: height 0.27, standoff -0.03, extent 3.35,-4.15 3.65,-3.85
3D body: height 0.27, standoff -0.03, extent 2.85,-4.15 3.15,-3.85
3D body: height 0.27, standoff -0.03, extent 2.35,-4.15 2.65,-3.85
3D body: height 0.27, standoff -0.03, extent 1.85,-4.15 2.15,-3.85
3D body: height 0.27, standoff -0.03, extent 1.35,-4.15 1.65,-3.85
3D body: height 0.27, standoff -0.03, extent 0.85,-4.15 1.15,-3.85
3D body: height 0.27, standoff -0.03, extent 0.35,-4.15 0.65,-3.85
3D body: height 0.27, standoff -0.03, extent -0.15,-4.15 0.15,-3.85
3D body: height 0.27, standoff -0.03, extent -0.65,-4.15 -0.35,-3.85
3D body: height 0.27, standoff -0.03, extent -1.15,-4.15 -0.85,-3.85
3D body: height 0.27, standoff -0.03, extent -1.65,-4.15 -1.35,-3.85
3D body: height 0.27, standoff -0.03, extent -2.15,-4.15 -1.85,-3.85
3D body: height 0.27, standoff -0.03, extent -2.65,-4.15 -2.35,-3.85
3D body: height 0.27, standoff -0.03, extent -3.15,-4.15 -2.85,-3.85
3D body: height 0.27, standoff -0.03, extent -3.65,-4.15 -3.35,-3.85
3D body: height 0.27, standoff -0.03, extent -4.15,-4.15 -3.85,-3.85
3D body: height 0.27, standoff -0.03, extent 3.85,-3.65 4.15,-3.35
3D body: height 0.27, standoff -0.03, extent 3.35,-3.65 3.65,-3.35
3D body: height 0.27, standoff -0.03, extent 2.85,-3.65 3.15,-3.35
3D body: height 0.27, standoff -0.03, extent 2.35,-3.65 2.65,-3.35
3D body: height 0.27, standoff -0.03, extent 1.85,-3.65 2.15,-3.35
3D body: height 0.27, standoff -0.03, extent 1.35,-3.65 1.65,-3.35
3D body: height 0.27, standoff -0.03, extent 0.85,-3.65 1.15,-3.35
3D body: height 0.27, standoff -0.03, extent 0.35,-3.65 0.65,-3.35
3D body: height 0.27, standoff -0.03, extent -0.15,-3.65 0.15,-3.35
3D body: height 0.27, standoff -0.03, extent -0.65,-3.65 -0.35,-3.35
3D body: height 0.27, standoff -0.03, extent -1.15,-3.65 -0.85,-3.35
3D body: height 0.27, standoff -0.03, extent -1.65,-3.65 -1.35,-3.35
3D body: height 0.27, standoff -0.03, extent -2.15,-3.65 -1.85,-3.35
3D body: height 0.27, standoff -0.03, extent -2.65,-3.65 -2.35,-3.35
3D body: height 0.27, standoff -0.03, extent -3.15,-3.65 -2.85,-3.35
3D body: height 0.27, standoff -0.03, extent -3.65,-3.65 -3.35,-3.35
3D body: height 0.27, standoff -0.03, extent -4.15,-3.65 -3.85,-3.35
3D body: height 0.27, standoff -0.03, extent 3.85,-3.15 4.15,-2.85
3D body: height 0.27, standoff -0.03, extent 3.35,-3.15 3.65,-2.85
3D body: height 0.27, standoff -0.03, extent 2.85,-3.15 3.15,-2.85
3D body: height 0.27, standoff -0.03, extent 2.35,-3.15 2.65,-2.85
3D body: height 0.27, standoff -0.03, extent 1.85,-3.15 2.15,-2.85
3D body: height 0.27, standoff -0.03, extent 1.35,-3.15 1.65,-2.85
3D body: height 0.27, standoff -0.03, extent 0.85,-3.15 1.15,-2.85
3D body: height 0.27, standoff -0.03, extent 0.35,-3.15 0.65,-2.85
3D body: height 0.27, standoff -0.03, extent -0.15,-3.15 0.15,-2.85
3D body: height 0.27, standoff -0.03, extent -0.65,-3.15 -0.35,-2.85
3D body: height 0.27, standoff -0.03, extent -1.15,-3.15 -0.85,-2.85
3D body: height 0.27, standoff -0.03, extent -1.65,-3.15 -1.35,-2.85
3D body: height 0.27, standoff -0.03, extent -2.15,-3.15 -1.85,-2.85
3D body: height 0.27, standoff -0.03, extent -2.65,-3.15 -2.35,-2.85
3D body: height 0.27, standoff -0.03, extent -3.15,-3.15 -2.85,-2.85
3D body: height 0.27, standoff -0.03, extent -3.65,-3.15 -3.35,-2.85
3D body: height 0.27, standoff -0.03, extent -4.15,-3.15 -3.85,-2.85
3D body: height 0.27, standoff -0.03, extent 3.85,-2.65 4.15,-2.35
3D body: height 0.27, standoff -0.03, extent 3.35,-2.65 3.65,-2.35
3D body: height 0.27, standoff -0.03, extent 2.85,-2.65 3.15,-2.35
3D body: height 0.27, standoff -0.03, extent 2.35,-2.65 2.65,-2.35
3D body: height 0.27, standoff -0.03, extent 1.85,-2.65 2.15,-2.35
3D body: height 0.27, standoff -0.03, extent 1.35,-2.65 1.65,-2.35
3D body: height 0.27, standoff -0.03, extent 0.85,-2.65 1.15,-2.35
3D body: height 0.27, standoff -0.03, extent 0.35,-2.65 0.65,-2.35
3D body: height 0.27, standoff -0.03, extent -0.15,-2.65 0.15,-2.35
3D body: height 0.27, standoff -0.03, extent -0.65,-2.65 -0.35,-2.35
3D body: height 0.27, standoff -0.03, extent -1.15,-2.65 -0.85,-2.35
3D body: height 0.27, standoff -0.03, extent -1.65,-2.65 -1.35,-2.35
3D body: height 0.27, standoff -0.03, extent -2.15,-2.65 -1.85,-2.35
3D body: height 0.27, standoff -0.03, extent -2.65,-2.65 -2.35,-2.35
3D body: height 0.27, standoff -0.03, extent -3.15,-2.65 -2.85,-2.35
3D body: height 0.27, standoff -0.03, extent -3.65,-2.65 -3.35,-2.35
3D body: height 0.27, standoff -0.03, extent -4.15,-2.65 -3.85,-2.35
3D body: height 0.27, standoff -0.03, extent 3.85,-2.15 4.15,-1.85
3D body: height 0.27, standoff -0.03, extent 3.35,-2.15 3.65,-1.85
3D body: height 0.27, standoff -0.03, extent 2.85,-2.15 3.15,-1.85
3D body: height 0.27, standoff -0.03, extent 2.35,-2.15 2.65,-1.85
3D body: height 0.27, standoff -0.03, extent 1.85,-2.15 2.15,-1.85
3D body: height 0.27, standoff -0.03, extent 1.35,-2.15 1.65,-1.85
3D body: height 0.27, standoff -0.03, extent 0.85,-2.15 1.15,-1.85
3D body: height 0.27, standoff -0.03, extent 0.35,-2.15 0.65,-1.85
3D body: height 0.27, standoff -0.03, extent -0.15,-2.15 0.15,-1.85
3D body: height 0.27, standoff -0.03, extent -0.65,-2.15 -0.35,-1.85
3D body: height 0.27, standoff -0.03, extent -1.15,-2.15 -0.85,-1.85
3D body: height 0.27, standoff -0.03, extent -1.65,-2.15 -1.35,-1.85
3D body: height 0.27, standoff -0.03, extent -2.15,-2.15 -1.85,-1.85
3D body: height 0.27, standoff -0.03, extent -2.65,-2.15 -2.35,-1.85
3D body: height 0.27, standoff -0.03, extent -3.15,-2.15 -2.85,-1.85
3D body: height 0.27, standoff -0.03, extent -3.65,-2.15 -3.35,-1.85
3D body: height 0.27, standoff -0.03, extent -4.15,-2.15 -3.85,-1.85
3D body: height 0.27, standoff -0.03, extent 3.85,-1.65 4.15,-1.35
3D body: height 0.27, standoff -0.03, extent 3.35,-1.65 3.65,-1.35
3D body: height 0.27, standoff -0.03, extent 2.85,-1.65 3.15,-1.35
3D body: height 0.27, standoff -0.03, extent 2.35,-1.65 2.65,-1.35
3D body: height 0.27, standoff -0.03, extent 1.85,-1.65 2.15,-1.35
3D body: height 0.27, standoff -0.03, extent 1.35,-1.65 1.65,-1.35
3D body: height 0.27, standoff -0.03, extent 0.85,-1.65 1.15,-1.35
3D body: height 0.27, standoff -0.03, extent 0.35,-1.65 0.65,-1.35
3D body: height 0.27, standoff -0.03, extent -0.15,-1.65 0.15,-1.35
3D body: height 0.27, standoff -0.03, extent -0.65,-1.65 -0.35,-1.35
3D body: height 0.27, standoff -0.03, extent -1.15,-1.65 -0.85,-1.35
3D body: height 0.27, standoff -0.03, extent -1.65,-1.65 -1.35,-1.35
3D body: height 0.27, standoff -0.03, extent -2.15,-1.65 -1.85,-1.35
3D body: height 0.27, standoff -0.03, extent -2.65,-1.65 -2.35,-1.35
3D body: height 0.27, standoff -0.03, extent -3.15,-1.65 -2.85,-1.35
3D body: height 0.27, standoff -0.03, extent -3.65,-1.65 -3.35,-1.35
3D body: height 0.27, standoff -0.03, extent -4.15,-1.65 -3.85,-1.35
3D body: height 0.27, standoff -0.03, extent 3.85,-1.15 4.15,-0.85
3D body: height 0.27, standoff -0.03, extent 3.35,-1.15 3.65,-0.85
3D body: height 0.27, standoff -0.03, extent 2.85,-1.15 3.15,-0.85
3D body: height 0.27, standoff -0.03, extent 2.35,-1.15 2.65,-0.85
3D body: height 0.27, standoff -0.03, extent 1.85,-1.15 2.15,-0.85
3D body: height 0.27, standoff -0.03, extent 1.35,-1.15 1.65,-0.85
3D body: height 0.27, standoff -0.03, extent 0.85,-1.15 1.15,-0.85
3D body: height 0.27, standoff -0.03, extent 0.35,-1.15 0.65,-0.85
3D body: height 0.27, standoff -0.03, extent -0.15,-1.15 0.15,-0.85
3D body: height 0.27, standoff -0.03, extent -0.65,-1.15 -0.35,-0.85
3D body: height 0.27, standoff -0.03, extent -1.15,-1.15 -0.85,-0.85
3D body: height 0.27, standoff -0.03, extent -1.65,-1.15 -1.35,-0.85
3D body: height 0.27, standoff -0.03, extent -2.15,-1.15 -1.85,-0.85
3D body: height 0.27, standoff -0.03, extent -2.65,-1.15 -2.35,-0.85
3D body: height 0.27, standoff -0.03, extent -3.15,-1.15 -2.85,-0.85
3D body: height 0.27, standoff -0.03, extent -3.65,-1.15 -3.35,-0.85
3D body: height 0.27, standoff -0.03, extent -4.15,-1.15 -3.85,-0.85
3D body: height 0.27, standoff -0.03, extent 3.85,-0.65 4.15,-0.35
3D body: height 0.27, standoff -0.03, extent 3.35,-0.65 3.65,-0.35
3D body: height 0.27, standoff -0.03, extent 2.85,-0.65 3.15,-0.35
3D body: height 0.27, standoff -0.03, extent 2.35,-0.65 2.65,-0.35
3D body: height 0.27, standoff -0.03, extent 1.85,-0.65 2.15,-0.35
3D body: height 0.27, standoff -0.03, extent 1.35,-0.65 1.65,-0.35
3D body: height 0.27, standoff -0.03, extent 0.85,-0.65 1.15,-0.35
3D body: height 0.27, standoff -0.03, extent 0.35,-0.65 0.65,-0.35
3D body: height 0.27, standoff -0.03, extent -0.15,-0.65 0.15,-0.35
3D body: height 0.27, standoff -0.03, extent -0.65,-0.65 -0.35,-0.35
3D body: height 0.27, standoff -0.03, extent -1.15,-0.65 -0.85,-0.35
3D body: height 0.27, standoff -0.03, extent -1.65,-0.65 -1.35,-0.35
3D body: height 0.27, standoff -0.03, extent -2.15,-0.65 -1.85,-0.35
3D body: height 0.27, standoff -0.03, extent -2.65,-0.65 -2.35,-0.35
3D body: height 0.27, standoff -0.03, extent -3.15,-0.65 -2.85,-0.35
3D body: height 0.27, standoff -0.03, extent -3.65,-0.65 -3.35,-0.35
3D body: height 0.27, standoff -0.03, extent -4.15,-0.65 -3.85,-0.35
3D body: height 0.27, standoff -0.03, extent 3.85,-0.15 4.15,0.15
3D body: height 0.27, standoff -0.03, extent 3.35,-0.15 3.65,0.15
3D body: height 0.27, standoff -0.03, extent 2.85,-0.15 3.15,0.15
3D body: height 0.27, standoff -0.03, extent 2.35,-0.15 2.65,0.15
3D body: height 0.27, standoff -0.03, extent 1.85,-0.15 2.15,0.15
3D body: height 0.27, standoff -0.03, extent 1.35,-0.15 1.65,0.15
3D body: height 0.27, standoff -0.03, extent 0.85,-0.15 1.15,0.15
3D body: height 0.27, standoff -0.03, extent 0.35,-0.15 0.65,0.15
3D body: height 0.27, standoff -0.03, extent -0.15,-0.15 0.15,0.15
3D body: height 0.27, standoff -0.03, extent -0.65,-0.15 -0.35,0.15
3D body: height 0.27, standoff -0.03, extent -1.15,-0.15 -0.85,0.15
3D body: height 0.27, standoff -0.03, extent -1.65,-0.15 -1.35,0.15
3D body: height 0.27, standoff -0.03, extent -2.15,-0.15 -1.85,0.15
3D body: height 0.27, standoff -0.03, extent -2.65,-0.15 -2.35,0.15
3D body: height 0.27, standoff -0.03, extent -3.15,-0.15 -2.85,0.15
3D body: height 0.27, standoff -0.03, extent -3.65,-0.15 -3.35,0.15
3D body: height 0.27, standoff -0.03, extent -4.15,-0.15 -3.85,0.15
3D body: height 0.27, standoff -0.03, extent 3.85,0.35 4.15,0.65
3D body: height 0.27, standoff -0.03, extent 3.35,0.35 3.65,0.65
3D body: height 0.27, standoff -0.03, extent 2.85,0.35 3.15,0.65
3D body: height 0.27, standoff -0.03, extent 2.35,0.35 2.65,0.65
3D body: height 0.27, standoff -0.03, extent 1.85,0.35 2.15,0.65
3D body: height 0.27, standoff -0.03, extent 1.35,0.35 1.65,0.65
3D body: height 0.27, standoff -0.03, extent 0.85,0.35 1.15,0.65
3D body: height 0.27, standoff -0.03, extent 0.35,0.35 0.65,0.65
3D body: height 0.27, standoff -0.03, extent -0.15,0.35 0.15,0.65
3D body: height 0.27, standoff -0.03, extent -0.65,0.35 -0.35,0.65
3D body: height 0.27, standoff -0.03, extent -1.15,0.35 -0.85,0.65
3D body: height 0.27, standoff -0.03, extent -1.65,0.35 -1.35,0.65
3D body: height 0.27, standoff -0.03, extent -2.15,0.35 -1.85,0.65
3D body: height 0.27, standoff -0.03, extent -2.65,0.35 -2.35,0.65
3D body: height 0.27, standoff -0.03, extent -3.15,0.35 -2.85,0.65
3D body: height 0.27, standoff -0.03, extent -3.65,0.35 -3.35,0.65
3D body: height 0.27, standoff -0.03, extent -4.15,0.35 -3.85,0.65
3D body: height 0.27, standoff -0.03, extent 3.85,0.85 4.15,1.15
3D body: height 0.27, standoff -0.03, extent 3.35,0.85 3.65,1.15
3D body: height 0.27, standoff -0.03, extent 2.85,0.85 3.15,1.15
3D body: height 0.27, standoff -0.03, extent 2.35,0.85 2.65,1.15
3D body: height 0.27, standoff -0.03, extent 1.85,0.85 2.15,1.15
3D body: height 0.27, standoff -0.03, extent 1.35,0.85 1.65,1.15
3D body: height 0.27, standoff -0.03, extent 0.85,0.85 1.15,1.15
3D body: height 0.27, standoff -0.03, extent 0.35,0.85 0.65,1.15
3D body: height 0.27, standoff -0.03, extent -0.15,0.85 0.15,1.15
3D body: height 0.27, standoff -0.03, extent -0.65,0.85 -0.35,1.15
3D body: height 0.27, standoff -0.03, extent -1.15,0.85 -0.85,1.15
3D body: height 0.27, standoff -0.03, extent -1.65,0.85 -1.35,1.15
3D body: height 0.27, standoff -0.03, extent -2.15,0.85 -1.85,1.15
3D body: height 0.27, standoff -0.03, extent -2.65,0.85 -2.35,1.15
3D body: height 0.27, standoff -0.03, extent -3.15,0.85 -2.85,1.15
3D body: height 0.27, standoff -0.03, extent -3.65,0.85 -3.35,1.15
3D body: height 0.27, standoff -0.03, extent -4.15,0.85 -3.85,1.15
3D body: height 0.27, standoff -0.03, extent 3.85,1.35 4.15,1.65
3D body: height 0.27, standoff -0.03, extent 3.35,1.35 3.65,1.65
3D body: height 0.27, standoff -0.03, extent 2.85,1.35 3.15,1.65
3D body: height 0.27, standoff -0.03, extent 2.35,1.35 2.65,1.65
3D body: height 0.27, standoff -0.03, extent 1.85,1.35 2.15,1.65
3D body: height 0.27, standoff -0.03, extent 1.35,1.35 1.65,1.65
3D body: height 0.27, standoff -0.03, extent 0.85,1.35 1.15,1.65
3D body: height 0.27, standoff -0.03, extent 0.35,1.35 0.65,1.65
3D body: height 0.27, standoff -0.03, extent -0.15,1.35 0.15,1.65
3D body: height 0.27, standoff -0.03, extent -0.65,1.35 -0.35,1.65
3D body: height 0.27, standoff -0.03, extent -1.15,1.35 -0.85,1.65
3D body: height 0.27, standoff -0.03, extent -1.65,1.35 -1.35,1.65
3D body: height 0.27, standoff -0.03, extent -2.15,1.35 -1.85,1.65
3D body: height 0.27, standoff -0.03, extent -2.65,1.35 -2.35,1.65
3D body: height 0.27, standoff -0.03, extent -3.15,1.35 -2.85,1.65
3D body: height 0.27, standoff -0.03, extent -3.65,1.35 -3.35,1.65
3D body: height 0.27, standoff -0.03, extent -4.15,1.35 -3.85,1.65
3D body: height 0.27, standoff -0.03, extent 3.85,1.85 4.15,2.15
3D body: height 0.27, standoff -0.03, extent 3.35,1.85 3.65,2.15
3D body: height 0.27, standoff -0.03, extent 2.85,1.85 3.15,2.15
3D body: height 0.27, standoff -0.03, extent 2.35,1.85 2.65,2.15
3D body: height 0.27, standoff -0.03, extent 1.85,1.85 2.15,2.15
3D body: height 0.27, standoff -0.03, extent 1.35,1.85 1.65,2.15
3D body: height 0.27, standoff -0.03, extent 0.85,1.85 1.15,2.15
3D body: height 0.27, standoff -0.03, extent 0.35,1.85 0.65,2.15
3D body: height 0.27, standoff -0.03, extent -0.15,1.85 0.15,2.15
3D body: height 0.27, standoff -0.03, extent -0.65,1.85 -0.35,2.15
3D body: height 0.27, standoff -0.03, extent -1.15,1.85 -0.85,2.15
3D body: height 0.27, standoff -0.03, extent -1.65,1.85 -1.35,2.15
3D body: height 0.27, standoff -0.03, extent -2.15,1.85 -1.85,2.15
3D body: height 0.27, standoff -0.03, extent -2.65,1.85 -2.35,2.15
3D body: height 0.27, standoff -0.03, extent -3.15,1.85 -2.85,2.15
3D body: height 0.27, standoff -0.03, extent -3.65,1.85 -3.35,2.15
3D body: height 0.27, standoff -0.03, extent -4.15,1.85 -3.85,2.15
3D body: height 0.27, standoff -0.03, extent 3.85,2.35 4.15,2.65
3D body: height 0.27, standoff -0.03, extent 3.35,2.35 3.65,2.65
3D body: height 0.27, standoff -0.03, extent 2.85,2.35 3.15,2.65
3D body: height 0.27, standoff -0.03, extent 2.35,2.35 2.65,2.65
3D body: height 0.27, standoff -0.03, extent 1.85,2.35 2.15,2.65
3D body: height 0.27, standoff -0.03, extent 1.35,2.35 1.65,2.65
3D body: height 0.27, standoff -0.03, extent 0.85,2.35 1.15,2.65
3D body: height 0.27, standoff -0.03, extent 0.35,2.35 0.65,2.65
3D body: height 0.27, standoff -0.03, extent -0.15,2.35 0.15,2.65
3D body: height 0.27, standoff -0.03, extent -0.65,2.35 -0.35,2.65
3D body: height 0.27, standoff -0.03, extent -1.15,2.35 -0.85,2.65
3D body: height 0.27, standoff -0.03, extent -1.65,2.35 -1.35,2.65
3D body: height 0.27, standoff -0.03, extent -2.15,2.35 -1.85,2.65
3D body: height 0.27, standoff -0.03, extent -2.65,2.35 -2.35,2.65
3D body: height 0.27, standoff -0.03, extent -3.15,2.35 -2.85,2.65
3D body: height 0.27, standoff -0.03, extent -3.65,2.35 -3.35,2.65
3D body: height 0.27, standoff -0.03, extent -4.15,2.35 -3.85,2.65
3D body: height 0.27, standoff -0.03, extent 3.85,2.85 4.15,3.15
3D body: height 0.27, standoff -0.03, extent 3.35,2.85 3.65,3.15
3D body: height 0.27, standoff -0.03, extent 2.85,2.85 3.15,3.15
3D body: height 0.27, standoff -0.03, extent 2.35,2.85 2.65,3.15
3D body: height 0.27, standoff -0.03, extent 1.85,2.85 2.15,3.15
3D body: height 0.27, standoff -0.03, extent 1.35,2.85 1.65,3.15
3D body: height 0.27, standoff -0.03, extent 0.85,2.85 1.15,3.15
3D body: height 0.27, standoff -0.03, extent 0.35,2.85 0.65,3.15
3D body: height 0.27, standoff -0.03, extent -0.15,2.85 0.15,3.15
3D body: height 0.27, standoff -0.03, extent -0.65,2.85 -0.35,3.15
3D body: height 0.27, standoff -0.03, extent -1.15,2.85 -0.85,3.15
3D body: height 0.27, standoff -0.03, extent -1.65,2.85 -1.35,3.15
3D body: height 0.27, standoff -0.03, extent -2.15,2.85 -1.85,3.15
3D body: height 0.27, standoff -0.03, extent -2.65,2.85 -2.35,3.15
3D body: height 0.27, standoff -0.03, extent -3.15,2.85 -2.85,3.15
3D body: height 0.27, standoff -0.03, extent -3.65,2.85 -3.35,3.15
3D body: height 0.27, standoff -0.03, extent -4.15,2.85 -3.85,3.15
3D body: height 0.27, standoff -0.03, extent 3.85,3.35 4.15,3.65
3D body: height 0.27, standoff -0.03, extent 3.35,3.35 3.65,3.65
3D body: height 0.27, standoff -0.03, extent 2.85,3.35 3.15,3.65
3D body: height 0.27, standoff -0.03, extent 2.35,3.35 2.65,3.65
3D body: height 0.27, standoff -0.03, extent 1.85,3.35 2.15,3.65
3D body: height 0.27, standoff -0.03, extent 1.35,3.35 1.65,3.65
3D body: height 0.27, standoff -0.03, extent 0.85,3.35 1.15,3.65
3D body: height 0.27, standoff -0.03, extent 0.35,3.35 0.65,3.65
3D body: height 0.27, standoff -0.03, extent -0.15,3.35 0.15,3.65
3D body: height 0.27, standoff -0.03, extent -0.65,3.35 -0.35,3.65
3D body: height 0.27, standoff -0.03, extent -1.15,3.35 -0.85,3.65
3D body: height 0.27, standoff -0.03, extent -1.65,3.35 -1.35,3.65
3D body: height 0.27, standoff -0.03, extent -2.15,3.35 -1.85,3.65
3D body: height 0.27, standoff -0.03, extent -2.65,3.35 -2.35,3.65
3D body: height 0.27, standoff -0.03, extent -3.15,3.35 -2.85,3.65
3D body: height 0.27, standoff -0.03, extent -3.65,3.35 -3.35,3.65
3D body: height 0.27, standoff -0.03, extent -4.15,3.35 -3.85,3.65
3D body: height 0.27, standoff -0.03, extent 3.85,3.85 4.15,4.15
3D body: height 0.27, standoff -0.03, extent 3.35,3.85 3.65,4.15
3D body: height 0.27, standoff -0.03, extent 2.85,3.85 3.15,4.15
3D body: height 0.27, standoff -0.03, extent 2.35,3.85 2.65,4.15
3D body: height 0.27, standoff -0.03, extent 1.85,3.85 2.15,4.15
3D body: height 0.27, standoff -0.03, extent 1.35,3.85 1.65,4.15
3D body: height 0.27, standoff -0.03, extent 0.85,3.85 1.15,4.15
3D body: height 0.27, standoff -0.03, extent 0.35,3.85 0.65,4.15
3D body: height 0.27, standoff -0.03, extent -0.15,3.85 0.15,4.15
3D body: height 0.27, standoff -0.03, extent -0.65,3.85 -0.35,4.15
3D body: height 0.27, standoff -0.03, extent -1.15,3.85 -0.85,4.15
3D body: height 0.27, standoff -0.03, extent -1.65,3.85 -1.35,4.15
3D body: height 0.27, standoff -0.03, extent -2.15,3.85 -1.85,4.15
3D body: height 0.27, standoff -0.03, extent -2.65,3.85 -2.35,4.15
3D body: height 0.27, standoff -0.03, extent -3.15,3.85 -2.85,4.15
3D body: height 0.27, standoff -0.03, extent -3.65,3.85 -3.35,4.15
3D body: height 1.2, standoff 0.2, extent -4.575,-4.575 4.575,4.575
3D body: height 0.27, standoff -0.03, extent -4.15,3.85 -3.85,4.15
3D body: height 1.21, standoff 1.2, extent -4.05,3.45 -3.45,4.05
